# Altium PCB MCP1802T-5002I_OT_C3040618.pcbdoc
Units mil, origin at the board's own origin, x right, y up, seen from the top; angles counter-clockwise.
Board outline 617.09 x 638.91 mil, 2 copper layers (Top Layer, Bottom Layer), stack 0 mil thick; 1 components, 0 nets, 5 pads, 0 vias.
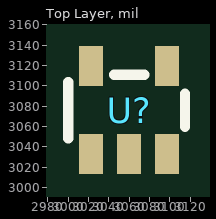
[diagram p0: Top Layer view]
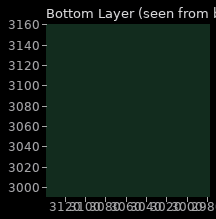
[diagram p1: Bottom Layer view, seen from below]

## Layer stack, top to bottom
Top Layer: signal copper (thickness not stored)
Bottom Layer: signal copper (thickness not stored)

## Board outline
3367.09,2750 2750,2750 2750,3388.91 3367.09,3388.91

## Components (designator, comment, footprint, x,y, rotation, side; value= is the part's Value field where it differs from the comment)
U? "MCP1802T-5002I/OT" SOT-23-5_L2.9-W1.6-P0.95-LS2.8-BL 3060,3075.91 r0 top

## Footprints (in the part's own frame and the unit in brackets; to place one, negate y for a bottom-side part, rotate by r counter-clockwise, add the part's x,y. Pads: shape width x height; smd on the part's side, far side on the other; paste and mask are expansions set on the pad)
SOT-23-5_L2.9-W1.6-P0.95-LS2.8-BL [mm]
  rect 0.6x1 smd paste+0 mask+0.05: 1(-0.95,-1.1) 2(0,-1.1) 3(0.95,-1.1) 4(0.95,1.1) 5(-0.95,1.1)
  silkscreen extent -1.52,-0.7 1.4,0.89

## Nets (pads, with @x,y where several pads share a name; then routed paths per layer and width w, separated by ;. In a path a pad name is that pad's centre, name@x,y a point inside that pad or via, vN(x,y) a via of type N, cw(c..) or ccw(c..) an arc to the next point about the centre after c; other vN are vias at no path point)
pads on no net: U?.1 U?.2 U?.3 U?.4 U?.5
